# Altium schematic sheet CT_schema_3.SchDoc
size 454 x 387 mm
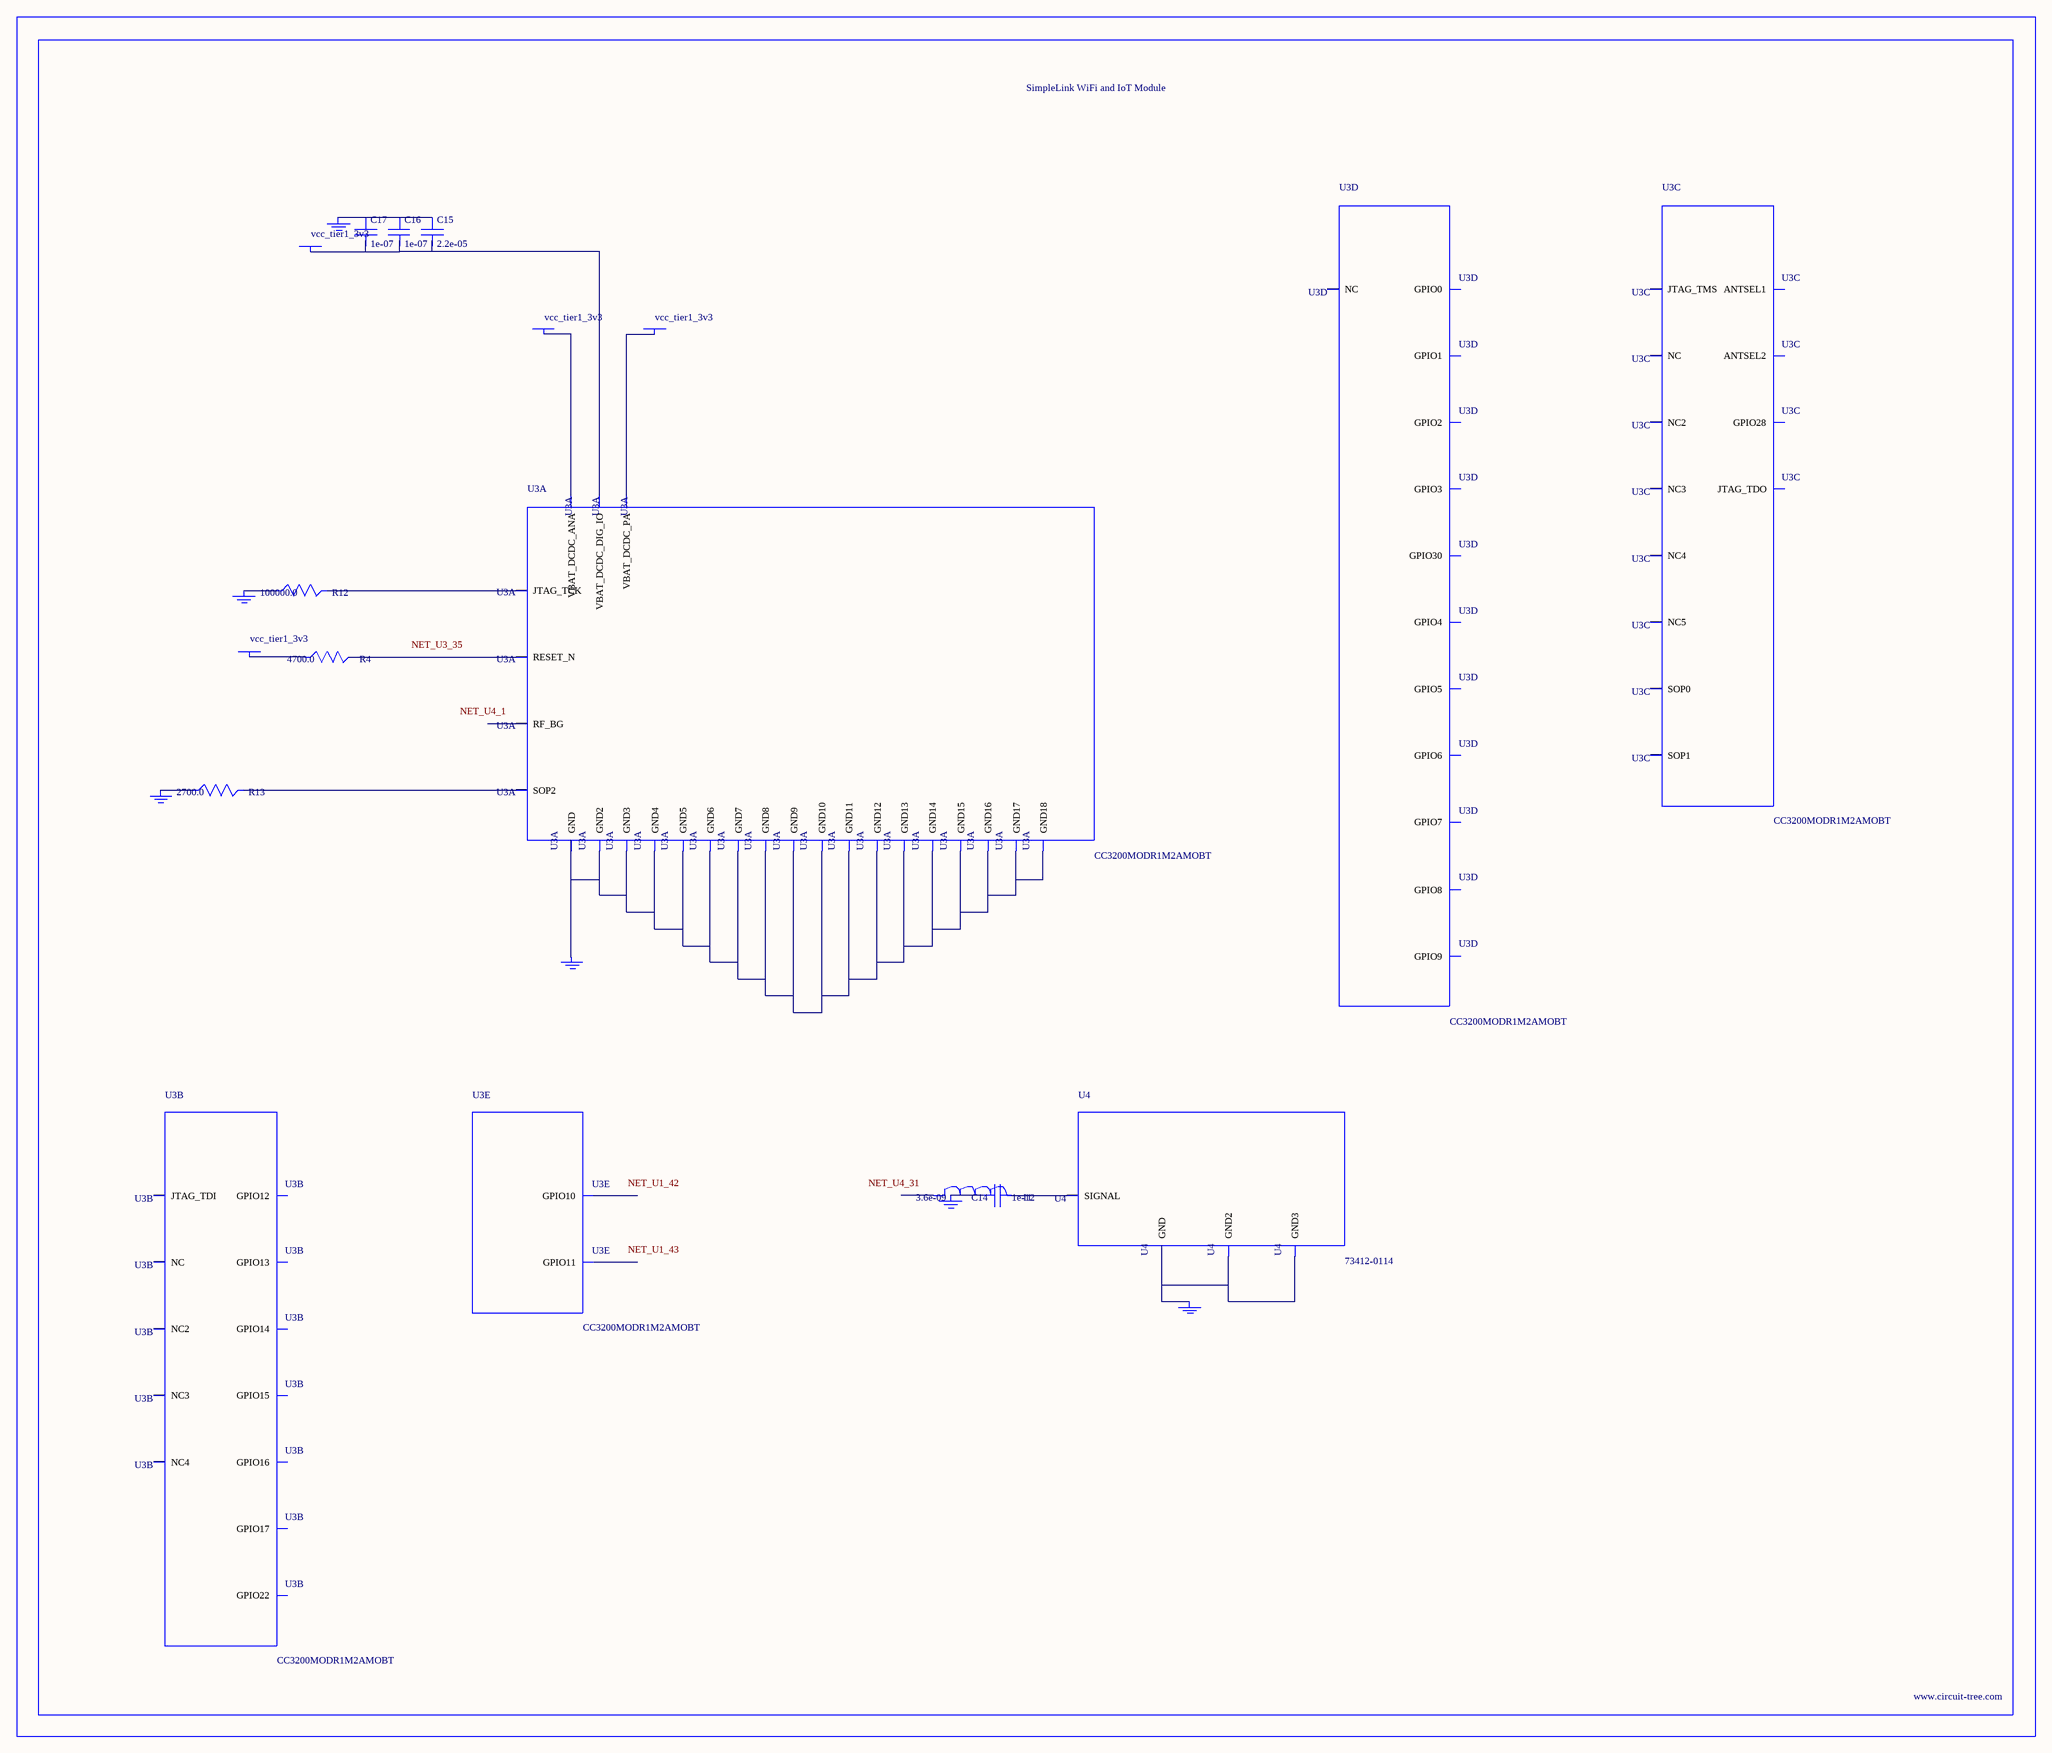
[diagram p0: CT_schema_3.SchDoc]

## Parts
BORDER2  (no value)
C14  1e-12  [C0402]
C15  2.2e-05  [C1210]
C16  1e-07  [C0402]
C17  1e-07  [C0402]
GND_INSTANCE_2_0  (no value)
GND_INSTANCE_2_1  (no value)
GND_INSTANCE_2_2  (no value)
GND_INSTANCE_2_3  (no value)
GND_INSTANCE_2_4  (no value)
GND_INSTANCE_2_5  (no value)
I1  3.6e-09  [C0402]
POWER_INSTANCE_2_0  vcc_tier1_3v3
POWER_INSTANCE_2_1  vcc_tier1_3v3
POWER_INSTANCE_2_2  vcc_tier1_3v3
POWER_INSTANCE_2_3  vcc_tier1_3v3
R4  4700.0  [R0603]
R12  100000.0  [R0603]
R13  2700.0  [R0603]
U3  CC3200MODR1M2AMOBT  [LGA63S127P16X13_2050X1750X150]  (parts A,B,C,D,E of 5)
U4  73412-0114  [COAXIAL_C]

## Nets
NetC14_1: C14.1 I1.2 U4.1(SIGNAL)
NetC14_2: C14.2 GND_INSTANCE_2_4.0(GND)
NetC15_1: C15.1 C16.1 C17.1 GND_INSTANCE_2_2.0(GND)
NetC15_2: C15.2 C16.2 C17.2 POWER_INSTANCE_2_2.0(PWR) U3.40(VBAT_DCDC_DIG_IO)
NetGND_INSTANCE_2_0_0: GND_INSTANCE_2_0.0(GND) R12.1
NetGND_INSTANCE_2_1_0: GND_INSTANCE_2_1.0(GND) R13.1
NetGND_INSTANCE_2_3_0: GND_INSTANCE_2_3.0(GND) U3.1(GND) U3.2(GND2) U3.16(GND3) U3.27(GND4) U3.28(GND5) U3.30(GND6) U3.32(GND7) U3.38(GND8) U3.43(GND9) U3.55(GND10) U3.56(GND11) U3.57(GND12) U3.58(GND13) U3.59(GND14) U3.60(GND15) U3.61(GND16) U3.62(GND17) U3.63(GND18)
NetGND_INSTANCE_2_5_0: GND_INSTANCE_2_5.0(GND) U4.2(GND) U4.3(GND2) U4.4(GND3)
NetPOWER_INSTANCE_2_0_0: POWER_INSTANCE_2_0.0(PWR) U3.36(VBAT_DCDC_ANA)
NetPOWER_INSTANCE_2_1_0: POWER_INSTANCE_2_1.0(PWR) U3.37(VBAT_DCDC_PA)
NetPOWER_INSTANCE_2_3_0: POWER_INSTANCE_2_3.0(PWR) R4.1
NetR4_2: R4.2 U3.35(RESET_N)
NetR12_2: R12.2 U3.21(JTAG_TCK)
NetR13_2: R13.2 U3.23(SOP2)

Not connected (* = marked no-connect by the designer): I1 1; U3 3(GPIO10) 4(GPIO11) 5(GPIO14) 6(GPIO15) 7(GPIO16) 8(GPIO17) 9(GPIO12) 10(GPIO13) 11(GPIO22) 12(JTAG_TDI) 13(NC) 14(NC2) 15(NC3) 17(NC4) 18(JTAG_TDO) 19(GPIO28) 20(NC) 22(JTAG_TMS) 24(SOP1) 25(ANTSEL1) 26(ANTSEL2) 29(NC2) 31(RF_BG) 33(NC3) 34(SOP0) 39(NC4) 41(NC5) 42(GPIO30) 44(GPIO0) 45(NC) 46(GPIO1) 47(GPIO2) 48(GPIO3) 49(GPIO4) 50(GPIO5) 51(GPIO6) 52(GPIO7) 53(GPIO8) 54(GPIO9)

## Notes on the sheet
- Labels drawn without touching a wire or pin: NET_U1_42, NET_U1_43, NET_U3_35, NET_U4_1, NET_U4_31

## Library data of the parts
BORDER2 = BORDER_PAGE2
C14 = C0402C109C3GACTU
C15 = C1210C224K5RACTU
C16 C17 = C0402C104K3RACTU
GND_INSTANCE_2_0-GND_INSTANCE_2_5 = GND
I1 = MCFT0BT3N6
POWER_INSTANCE_2_0-POWER_INSTANCE_2_3 = PWR
R4 = RC0603JR-074K7L
R12 = RC0603JR-07100KL
R13 = RC0603JR-072K7L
